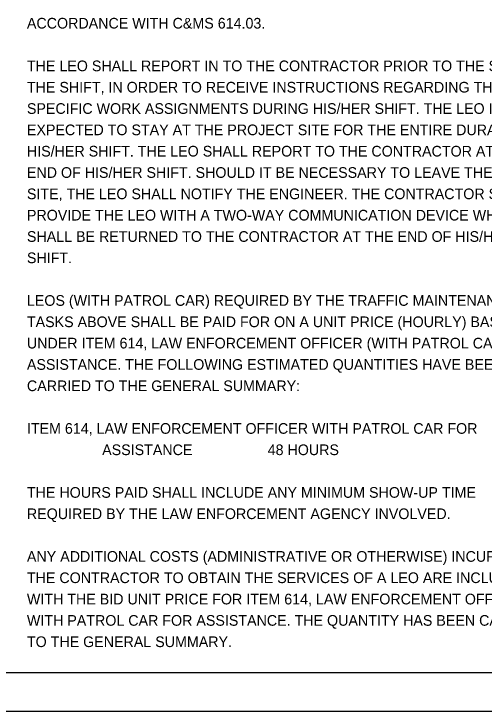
# Model space of a CAD drawing. Extents: x 0 to 34, y 0 to 22.
# Drawn here: x 24.49 to 30.66, y 0 to 9.15 of the extents above; entities that cross this region are included whole.
import ezdxf

# ---------------------------------------------------------------- set-up
doc = ezdxf.new("R2010")
doc.units = 0
for name, color, linetype in [('SH_Border', 7, 'Continuous'), ('SH_Cut_Line', 7, 'Continuous'), ('SH_Text', 7, 'Continuous')]:
    doc.layers.add(name, color=color, linetype=linetype)

msp = doc.modelspace()

# ---------------------------------------------------------------- linework, layer by layer
at = {"layer": 'SH_Border'}
msp.add_lwpolyline([(1.5, 21.5), (33.5, 21.5), (33.5, 0.5), (1.5, 0.5)], close=True, dxfattribs=at)
at = {"layer": 'SH_Cut_Line'}
msp.add_lwpolyline([(0, 0), (34, 0), (34, 22), (0, 22)], close=True, dxfattribs=at)

# ---------------------------------------------------------------- texts
at = {"layer": 'SH_Text'}
for s, p in [('ACCORDANCE WITH C&MS 614.03.', (24.66, 8.96)), ('THE LEO SHALL REPORT IN TO THE CONTRACTOR PRIOR TO THE START OF ', (24.66, 8.4)), ('THE SHIFT, IN ORDER TO RECEIVE INSTRUCTIONS REGARDING THE ', (24.66, 8.12)), ('SPECIFIC WORK ASSIGNMENTS DURING HIS/HER SHIFT. THE LEO IS', (24.66, 7.84)), ('EXPECTED TO STAY AT THE PROJECT SITE FOR THE ENTIRE DURATION OF ', (24.66, 7.56)), ('HIS/HER SHIFT. THE LEO SHALL REPORT TO THE CONTRACTOR AT THE ', (24.66, 7.28)), ('END OF HIS/HER SHIFT. SHOULD IT BE NECESSARY TO LEAVE THE PROJECT', (24.66, 7)), ('SITE, THE LEO SHALL NOTIFY THE ENGINEER. THE CONTRACTOR SHALL ', (24.66, 6.72)), ('PROVIDE THE LEO WITH A TWO-WAY COMMUNICATION DEVICE WHICH ', (24.66, 6.44)), ('SHALL BE RETURNED TO THE CONTRACTOR AT THE END OF HIS/HER ', (24.66, 6.16)), ('SHIFT.', (24.66, 5.88)), ('LEOS (WITH PATROL CAR) REQUIRED BY THE TRAFFIC MAINTENANCE ', (24.66, 5.32)), ('TASKS ABOVE SHALL BE PAID FOR ON A UNIT PRICE (HOURLY) BASIS ', (24.66, 5.04)), ('UNDER ITEM 614, LAW ENFORCEMENT OFFICER (WITH PATROL CAR) FOR', (24.66, 4.76)), ('ASSISTANCE. THE FOLLOWING ESTIMATED QUANTITIES HAVE BEEN ', (24.66, 4.48)), ('CARRIED TO THE GENERAL SUMMARY:', (24.66, 4.2)), ('ITEM 614, LAW ENFORCEMENT OFFICER WITH PATROL CAR FOR', (24.66, 3.64)), ('                   ASSISTANCE                   48 HOURS', (24.66, 3.36)), ('THE HOURS PAID SHALL INCLUDE ANY MINIMUM SHOW-UP TIME ', (24.66, 2.8)), ('REQUIRED BY THE LAW ENFORCEMENT AGENCY INVOLVED.', (24.66, 2.52)), ('ANY ADDITIONAL COSTS (ADMINISTRATIVE OR OTHERWISE) INCURRED BY ', (24.66, 1.96)), ('THE CONTRACTOR TO OBTAIN THE SERVICES OF A LEO ARE INCLUDED ', (24.66, 1.68)), ('WITH THE BID UNIT PRICE FOR ITEM 614, LAW ENFORCEMENT OFFICER ', (24.66, 1.4)), ('WITH PATROL CAR FOR ASSISTANCE. THE QUANTITY HAS BEEN CARRIED ', (24.66, 1.12)), ('TO THE GENERAL SUMMARY.', (24.66, 0.84))]:
    msp.add_text(s, height=0.14, dxfattribs=at).set_placement(p)

doc.saveas('drawing.dxf')
